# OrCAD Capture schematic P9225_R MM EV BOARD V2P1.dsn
size Custom; title: P9225-R MM EV Board; rev: 2.1; note: P10331
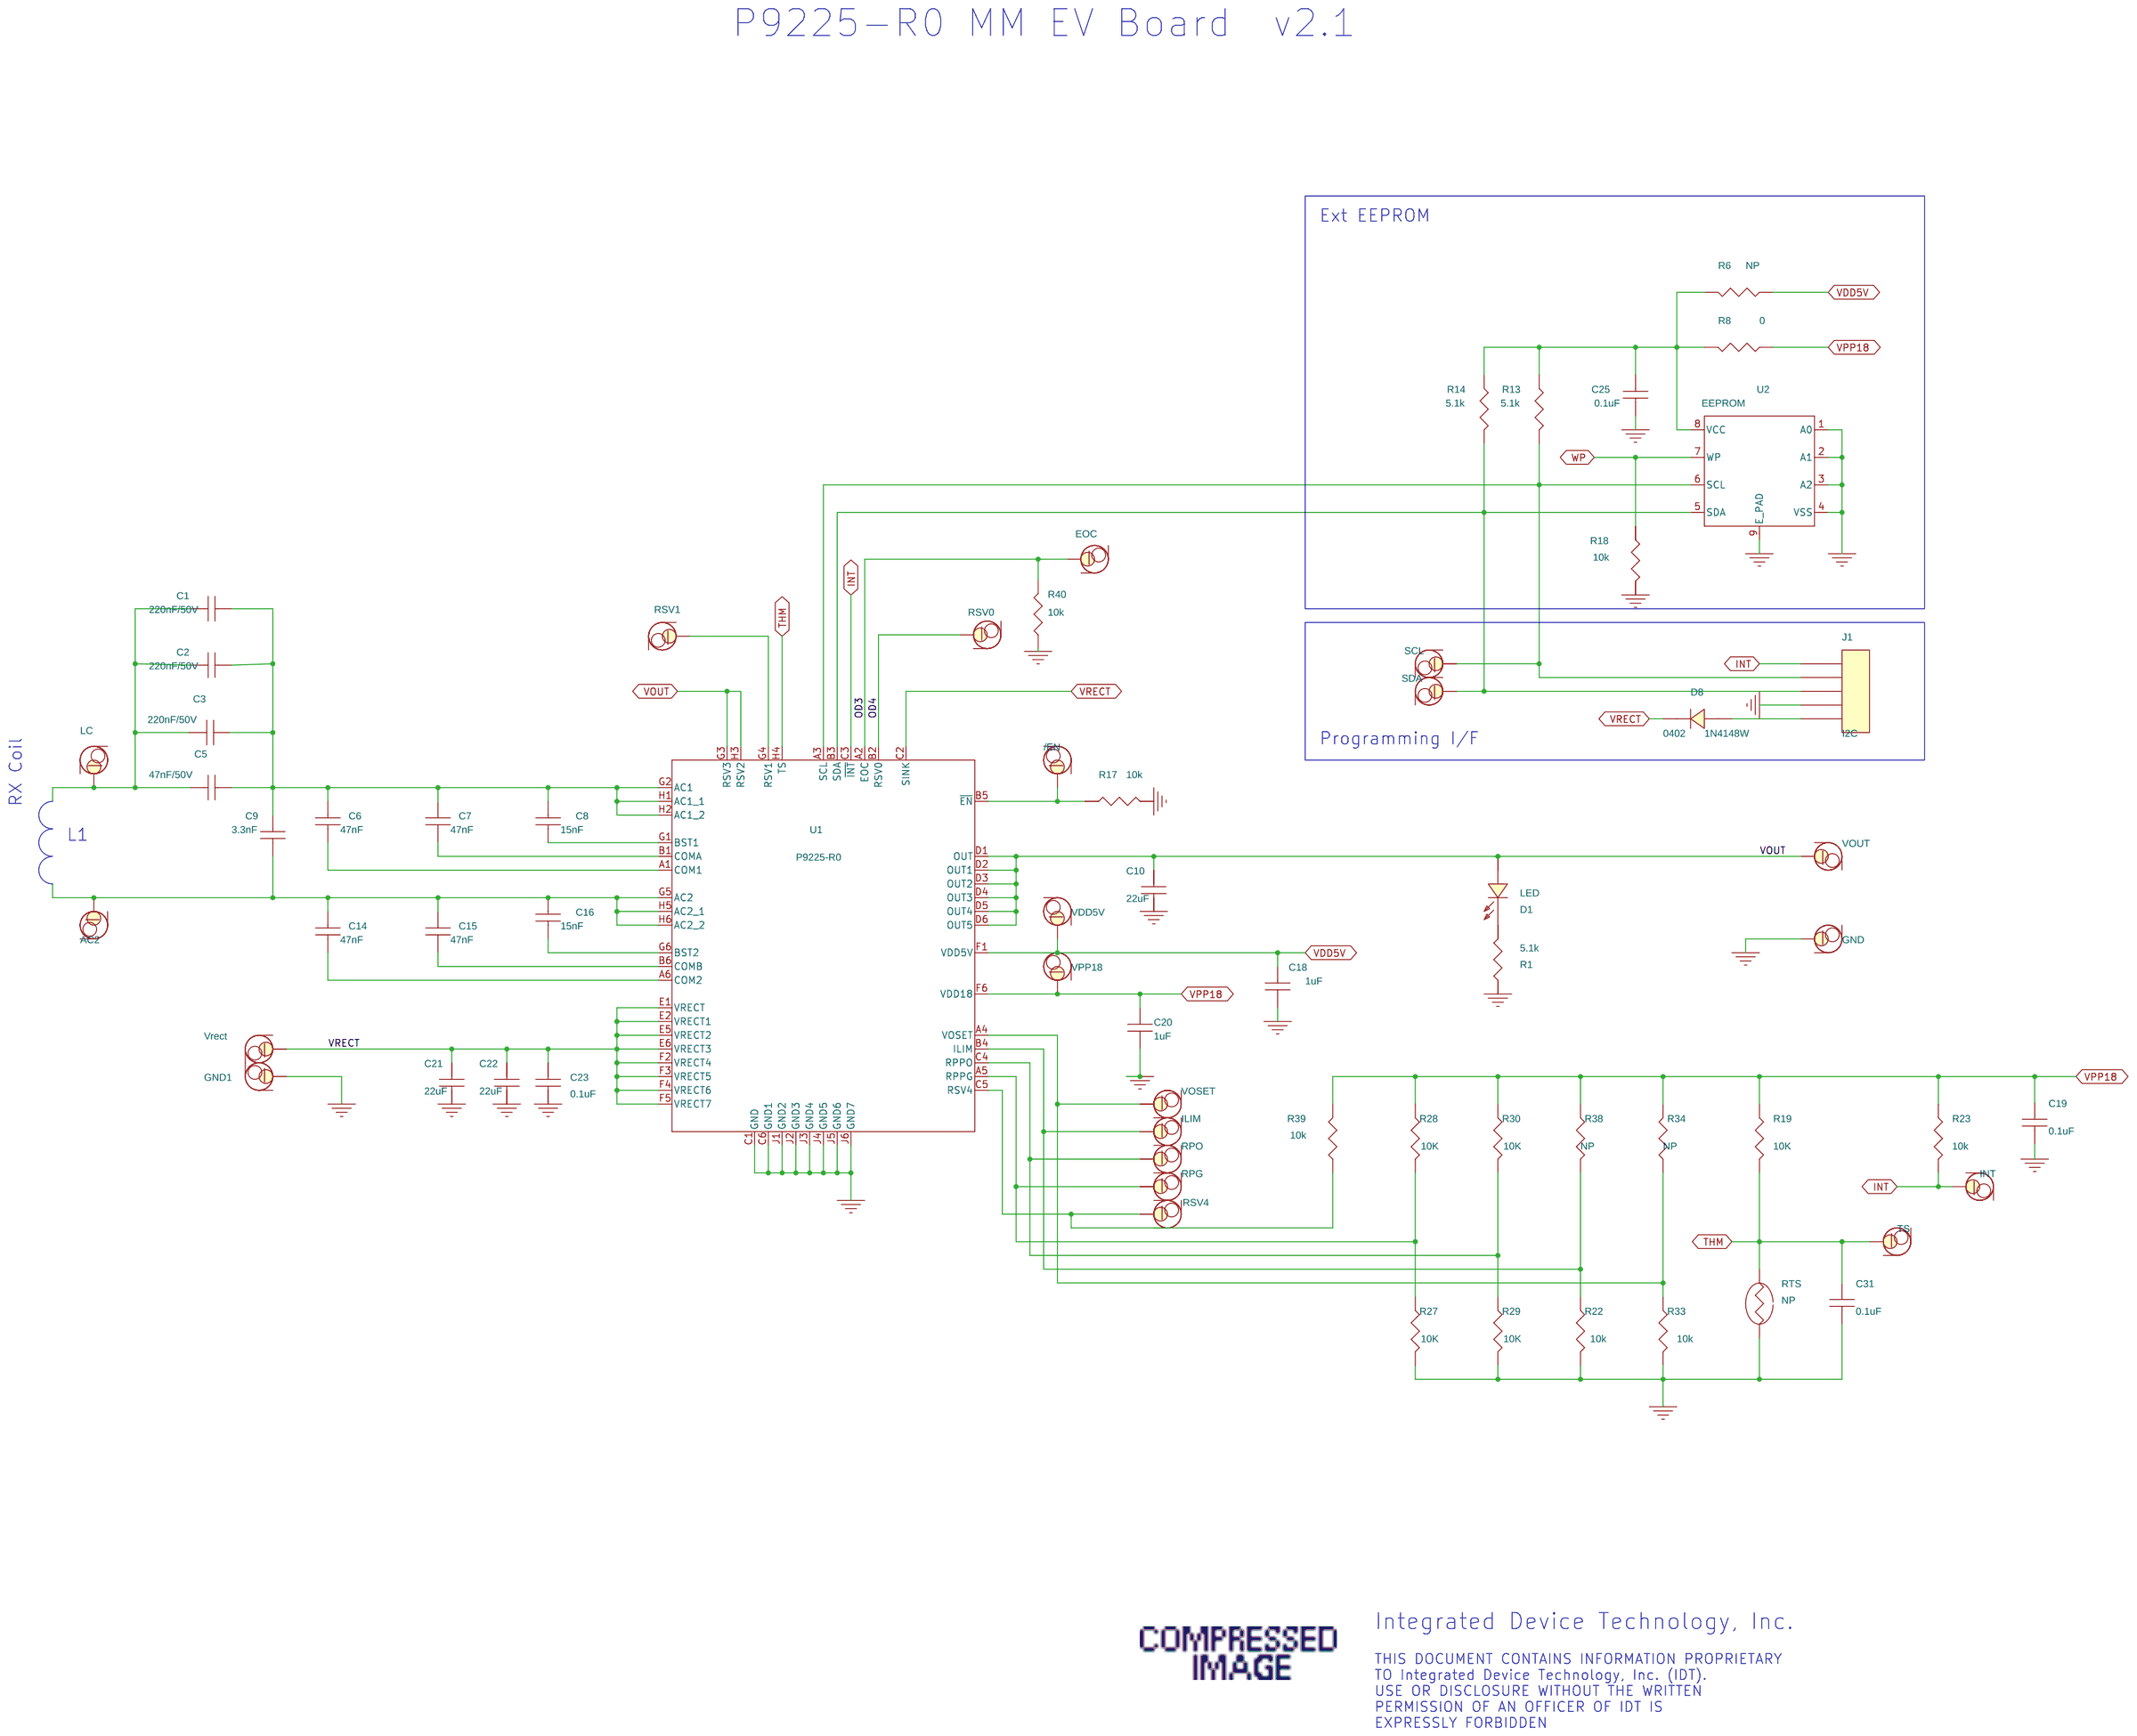
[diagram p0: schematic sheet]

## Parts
/EN  PTH_TP  [40MIL_60PAD]
AC2  NP  [test_pt_sm_135x70]
C1  220nF/50V  [0603]
C2  220nF/50V  [0603]
C3  220nF/50V  [0603]
C5  47nF/50V  [0402]
C6  47nF  [0402]
C7  47nF  [0402]
C8  15nF  [0402]
C9  3.3nF  [0402]
C10  22uF  [0805]
C14  47nF  [0402]
C15  47nF  [0402]
C16  15nF  [0402]
C18  1uF  [0402]
C19  0.1uF  [0201]
C20  1uF  [0402]
C21  22uF  [0805]
C22  22uF  [0805]
C23  0.1uF  [0201]
C25  0.1uF  [0201]
C31  0.1uF  [0201]
D1  LED  [0603_diode]
D8  1N4148W  [0402]
EOC  PTH_TP  [40MIL_60PAD]
GND  Test Point  [test_pt_sm_135x70]
GND1  Test Point  [test_pt_sm_135x70]
ILIM  PTH_TP  [40MIL_60PAD]
INT  PTH_TP  [40MIL_60PAD]
J1  I2C  [header_1x5_0p1Pitch60p42d]
LC  NP  [test_pt_sm_135x70]
R1  5.1k  [0402]
R6  NP  [0402]
R8  0  [0402]
R13  5.1k  [0402]
R14  5.1k  [0402]
R17  10k  [0201]
R18  10k  [0201]
R19  10K  [0201]
R22  10k  [0201]
R23  10k  [0201]
R27  10K  [0201]
R28  10K  [0201]
R29  10K  [0201]
R30  10K  [0201]
R33  10k  [0201]
R34  NP  [0201]
R38  NP  [0201]
R39  10k  [0201]
R40  10k  [0201]
RPG  PTH_TP  [40MIL_60PAD]
RPO  PTH_TP  [40MIL_60PAD]
RSV0  PTH_TP  [40MIL_60PAD]
RSV1  PTH_TP  [40MIL_60PAD]
RSV4  PTH_TP  [40MIL_60PAD]
RTS  NP  [NTC2]
SCL  PTH_TP  [10MIL_35PAD]
SDA  PTH_TP  [10MIL_35PAD]
TS  PTH_TP  [10MIL_35PAD]
U1  P9225-R0  [csp52_2p64x3p94_0p4mm]
U2  EEPROM  [TDFN08]
VDD5V  PTH_TP  [40MIL_60PAD]
VOSET  PTH_TP  [40MIL_60PAD]
VOUT  Test Point  [test_pt_sm_135x70]
VPP18  PTH_TP  [40MIL_60PAD]
Vrect  Test Point  [test_pt_sm_135x70]

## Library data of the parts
/EN EOC ILIM INT RPG RPO RSV0 RSV1 RSV4 SCL SDA TS VDD5V VOSET VPP18 = PTH_TP: Test Pad
AC2 LC = PTH_TP: TEST POINT
C1-C3 = CAP_NP: CAP CER 0.22UF 50V X7R 0603; Part Number: GRM188R71H224KAC4D
C5-C7 C14 C15 = CAP_NP: CAP CER 0.047UF 50V X7R 0402; Part Number: GRM155R71H473KE14D
C8 C16 = CAP_NP: CAP CER 0.015UF 50V X7R 0402; Part Number: GRM155R71H153KA12J
C9 = CAP_NP: CAP CER 3300PF 50V X7R 0402; Part Number: GRM155R71H332KA01D
C10 = CAP_NP: CAP CER 22UF 16V X5R 0805; Part Number: CL21A226MOCLRNC
C18 C20 = CAP_NP: CAP CER 1UF 10V X5R 0402; Part Number: GRM155R61A105KE15D
C19 C25 C31 = CAP_NP: CAP CER 0.1UF 10V X5R 0201; Part Number: GRM155R61A104KA01J
C21 C22 = CAP_NP: CAP CER 22UF 25V X5R 0805; Part Number: CL21A226MAQNNNE
C23 = CAP_NP: CAP CER 0.1UF 25V X5R 0201; Part Number: GRM155R61E104KA87D
D1 = LED_0: LED GREEN CLEAR 0603 SMD; Part Number: 150 060 GS7 500 0
D8 = DIODE_0: DFN 150mA 75V Sm Sgnl Switching; PART NUMBER: CDSQR4148
GND GND1 VOUT Vrect = PTH_TP: TEST POINT PC MINIATURE SMT; Part Number: 5015; Part_Number: 5015
J1 = CON5: HEADER_1X5_0P1PITCH60P42D; Part Number: 68002-205HLF
R1 R13 R14 = RESISTOR: RES SMD 5.1K OHM 5% 1/16W 0402; Part Number: MCR01MRTJ512
R6 = RESISTOR: RES SMD 0.0OHM JUMPER; Part Number: ERJ-2GE0R00X
R8 = RESISTOR: RES SMD 0.0OHM JUMPER 1/10W 0402; Part Number: ERJ-2GE0R00X
R17 R18 R23 R39 R40 = RESISTOR: RES SMD 10K OHM 5% 1/16W 0402; Part Number: ERJ-1GEJ103C
R19 = RESISTOR: RES SMD 47K OHM 1% 1/16W 0402; Part Number: ERJ-1GEF1002C
R22 R27-R30 R33 R34 R38 = RESISTOR: RES SMD 10K OHM 1% 1/16W 0402; Part Number: ERJ-1GEF1002C
RTS = RESISTOR_0
U1 = IDTP9220_CSP_13: MP Wireless power receiver; Part Number: P9225-X
U2 = 24LC128_0: IC EEPROM 128KBIT 400KHZ 8TDFN; Part Number: 24AA128T-I/MNY

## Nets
GND_POWER: C10.2 C18.2 C19.2 C20.2 C21.2 C22.2 C23.2 C25.2 C31.2 GND.1 GND1.1 J1.4 R1.1 R17.2 R18.1 R22.1 R27.1 R29.1 R33.1 R40.1 RTS.2 U1.C1(GND) U1.C6(GND1) U1.J1(GND2) U1.J2(GND3) U1.J3(GND4) U1.J4(GND5) U1.J5(GND6) U1.J6(GND7) U2.1(A0) U2.2(A1) U2.3(A2) U2.4(VSS) U2.9(E_PAD)
VDD5V: C18.1 R6.2 U1.F1(VDD5V) VDD5V.1
INT: INT.1 J1.1 R23.1 U1.C3(~{INT})
OD3: EOC.1 R40.2 U1.A2(EOC)
OD4: RSV0.1 U1.B2(RSV0)
THM: C31.1 R19.2 RTS.1 TS.1 U1.H4(TS)
VOUT: C10.1 D1.1(ANODE) U1.D1(OUT) U1.D2(OUT1) U1.D3(OUT2) U1.D4(OUT3) U1.D5(OUT4) U1.D6(OUT5) U1.G3(RSV3) U1.H3(RSV2) VOUT.1
VPP18: C19.1 C20.1 R8.2 R19.1 R23.2 R28.2 R30.2 R34.1 R38.2 R39.2 U1.F6(VDD18) VPP18.1
VRECT: C21.1 C22.1 C23.1 D8.2(K) U1.C2(SINK) U1.E1(VRECT) U1.E2(VRECT1) U1.E5(VRECT2) U1.E6(VRECT3) U1.F2(VRECT4) U1.F3(VRECT5) U1.F4(VRECT6) U1.F5(VRECT7) Vrect.1
WP: R18.2 U2.7(WP)
N7563167: /EN.1 R17.1 U1.B5(~{EN})
N7563825: C15.2 U1.B6(COMB)
N7563835: C14.2 U1.A6(COM2)
N7563843: AC2.1 C9.2 C14.1 C15.1 C16.1 U1.G5(AC2) U1.H5(AC2_1) U1.H6(AC2_2)
N7563887: C8.2 U1.G1(BST1)
N7563891: C6.2 U1.A1(COM1)
N7563895: C1.1 C2.1 C3.1 C5.1 C6.1 C7.1 C8.1 C9.1 U1.G2(AC1) U1.H1(AC1_1) U1.H2(AC1_2)
N7564147: C1.2 C2.2 C3.2 C5.2 LC.1
N7564207: C7.2 U1.B1(COMA)
N7564297: C25.1 R6.1 R8.1 R13.2 R14.2 U2.8(VCC)
N7564401: R27.2 R28.1 RPG.1 U1.A5(RPPG)
N7564413: ILIM.1 R22.2 R38.1 U1.B4(ILIM)
N7564491: J1.2 R13.1 SCL.1 U1.A3(SCL) U2.6(SCL)
N7564497: J1.3 R14.1 SDA.1 U1.B3(SDA) U2.5(SDA)
N7564631: R33.2 R34.2 U1.A4(VOSET) VOSET.1
N7566649: R39.1 RSV4.1 U1.C5(RSV4)
N7566662: R29.2 R30.1 RPO.1 U1.C4(RPPO)
N8120855: C16.2 U1.G6(BST2)
N8141222: D1.2(CATHODE) R1.2
N16756161: D8.1(A) J1.5
N16788637: RSV1.1 U1.G4(RSV1)

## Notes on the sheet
- P9225-R0 MM EV Board  v2.1
- Ext EEPROM
- Programming I/F
- RX Coil
- L1
- Integrated Device Technology, Inc.
- THIS DOCUMENT CONTAINS INFORMATION PROPRIETARY
  TO Integrated Device Technology, Inc. (IDT).
  USE OR DISCLOSURE WITHOUT THE WRITTEN
  PERMISSION OF AN OFFICER OF IDT IS
  EXPRESSLY FORBIDDEN
